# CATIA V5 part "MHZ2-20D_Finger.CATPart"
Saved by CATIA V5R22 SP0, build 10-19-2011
Part number: MHZ2-20D_Finger
Property "ParasolidId": 9
Property "PSOL_INSTNR": 3
Property "ParasolidId": 6
Property "PSOL_INSTNR": 3
Bounding box of the stored display mesh (mm): x -24.69 to -5.19, y -6.388 to 6.388, z -1 to 27.1
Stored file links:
  U:\S9A\PER\CAO\Assemblage\Cadre\Chariot_Y\Prehenseur\MHZ2-20D_Finger.CATPart
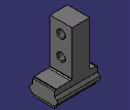
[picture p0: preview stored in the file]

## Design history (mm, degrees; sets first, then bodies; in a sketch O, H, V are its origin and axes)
Body1 "MHZ2-20D_Finger" (main body)
  Solid1: solid without history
